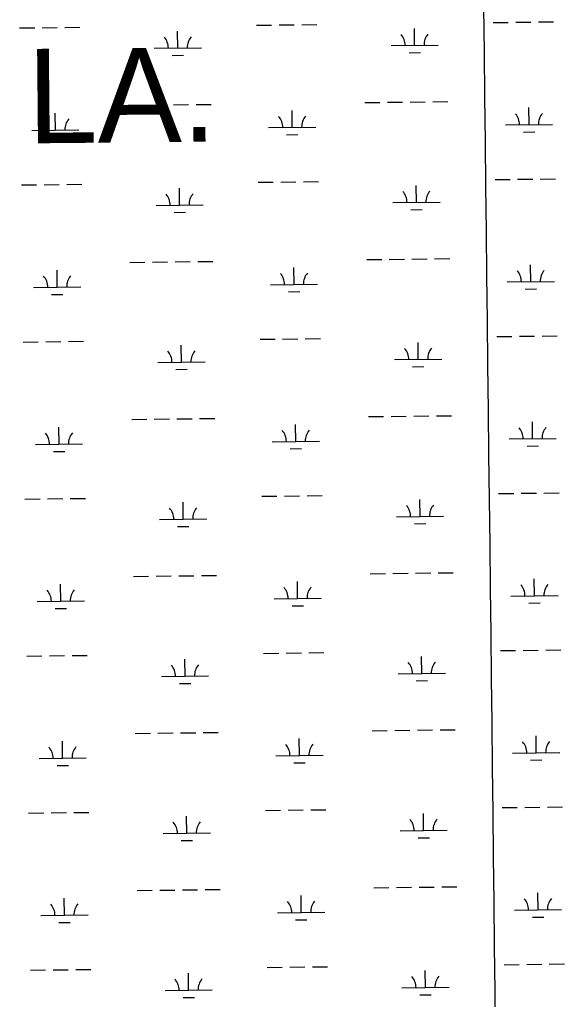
# Model space of a CAD drawing. Extents: x 3678539 to 3716648, y 451386 to 477139.
# Drawn here: x 3686961 to 3688116, y 464890 to 466966 of the extents above; entities that cross this region are included whole.
import ezdxf

# ---------------------------------------------------------------- set-up
doc = ezdxf.new("R2010")
doc.units = 0
for name, color, linetype in [('V-GRID-MAJR', 7, 'Continuous'), ('V-TOPO-GNAM-IDEN', 7, 'Continuous'), ('V-WETL-SWMP', 7, 'Continuous')]:
    doc.layers.add(name, color=color, linetype=linetype)

msp = doc.modelspace()

# ---------------------------------------------------------------- linework, layer by layer
at = {"layer": 'V-GRID-MAJR'}
msp.add_spline([(3688058.923, 456860.782), (3687991.068, 462919.335), (3687923.191, 468979.818), (3687855.313, 475040.309), (3687855.291, 475042.231)], degree=3, dxfattribs=at)
at = {"layer": 'V-WETL-SWMP'}
for p, q in [((3686961.1525815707, 466948.31695062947), (3686993.1504564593, 466948.68463293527)), ((3687009.1493939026, 466948.86847408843), (3687041.1472687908, 466949.2361563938)), ((3687057.146206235, 466949.41999754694), (3687089.1440811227, 466949.7876798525)), ((3687463.027249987, 466954.08390971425), (3687495.0251248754, 466954.45159202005)), ((3687511.0240623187, 466954.6354331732), (3687543.0219372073, 466955.00311547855)), ((3687559.020874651, 466955.18695663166), (3687591.018749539, 466955.55463893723)), ((3687798.382506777, 466911.5043577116), (3687797.968856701, 466947.5019802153)), ((3687964.9019184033, 466959.8508687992), (3687996.8997932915, 466960.218551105)), ((3688012.8987307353, 466960.40239225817), (3688044.8966056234, 466960.7700745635)), ((3688060.8955430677, 466960.9539157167), (3688092.8934179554, 466961.32159802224)), ((3687296.5078383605, 466905.7373986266), (3687296.094188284, 466941.73502113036)), ((3687246.5111588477, 466905.1628950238), (3687346.504517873, 466906.3119022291)), ((3687748.3858272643, 466910.92985410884), (3687848.3791862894, 466912.07886131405)), ((3687284.6859417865, 466890.1695368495), (3687308.684347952, 466890.445298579)), ((3687786.560610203, 466895.9364959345), (3687810.5590163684, 466896.21225766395)), ((3687191.0505832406, 466784.4466830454), (3687223.0484581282, 466784.8143653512)), ((3687239.047395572, 466784.99820650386), (3687271.04527046, 466785.3658888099)), ((3687287.0442079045, 466785.54972996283), (3687319.042082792, 466785.9174122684)), ((3687335.0410202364, 466786.10125342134), (3687367.0388951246, 466786.46893572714)), ((3687692.9252516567, 466790.2136421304), (3687724.923126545, 466790.5813244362)), ((3687740.9220639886, 466790.7651655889), (3687772.919938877, 466791.1328478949)), ((3687788.918876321, 466791.31668904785), (3687820.916751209, 466791.6843713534)), ((3687836.915688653, 466791.8682125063), (3687868.9135635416, 466792.2358948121)), ((3688040.801226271, 466743.4656790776), (3688040.387576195, 466779.4633015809)), ((3687037.051889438, 466731.9317609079), (3687036.6382393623, 466767.9293834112)), ((3687538.9265578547, 466737.69871999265), (3687538.512907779, 466773.6963424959)), ((3687488.929878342, 466737.1242163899), (3687588.9232373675, 466738.2732235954)), ((3687990.8045467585, 466742.8911754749), (3688090.7979057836, 466744.04018268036)), ((3686987.055209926, 466731.3572573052), (3687087.0485689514, 466732.5062645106)), ((3687025.229992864, 466716.3638991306), (3687049.22839903, 466716.6396608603)), ((3687527.1046612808, 466722.1308582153), (3687551.1030674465, 466722.4066199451)), ((3688028.979329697, 466727.89781730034), (3688052.9777358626, 466728.17357903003)), ((3686964.9751104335, 466615.66392100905), (3686996.972985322, 466616.0316033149)), ((3687012.971922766, 466616.215444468), (3687044.9697976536, 466616.58312677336)), ((3687060.968735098, 466616.7669679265), (3687092.9666099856, 466617.1346502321)), ((3687466.8497788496, 466621.43088009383), (3687498.847653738, 466621.79856239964)), ((3687514.846591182, 466621.9824035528), (3687546.84446607, 466622.35008585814)), ((3687562.843403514, 466622.53392701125), (3687594.841278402, 466622.9016093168)), ((3687802.20503564, 466578.8513280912), (3687801.791385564, 466614.8489505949)), ((3687968.724447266, 466627.1978391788), (3688000.722322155, 466627.56552148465)), ((3688016.721259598, 466627.74936263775), (3688048.7191344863, 466628.1170449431)), ((3688064.7180719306, 466628.30088609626), (3688096.7159468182, 466628.66856840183)), ((3687300.3303672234, 466573.08436900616), (3687299.916717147, 466609.08199150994)), ((3687250.333687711, 466572.5098654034), (3687350.3270467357, 466573.6588726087)), ((3687752.208356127, 466578.2768244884), (3687852.2017151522, 466579.42583169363)), ((3687288.5084706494, 466557.5165072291), (3687312.506876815, 466557.7922689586)), ((3687790.383139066, 466563.2834663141), (3687814.381545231, 466563.55922804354)), ((3687194.8731121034, 466451.793653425), (3687226.870986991, 466452.1613357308)), ((3687242.8699244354, 466452.34517688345), (3687274.867799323, 466452.71285918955)), ((3687290.8667367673, 466452.8967003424), (3687322.8646116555, 466453.264382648)), ((3687338.8635490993, 466453.4482238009), (3687370.8614239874, 466453.8159061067)), ((3687696.7477805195, 466457.56061250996), (3687728.745655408, 466457.92829481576)), ((3687744.7445928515, 466458.11213596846), (3687776.74246774, 466458.4798182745)), ((3687792.741405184, 466458.66365942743), (3687824.7392800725, 466459.031341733)), ((3687840.738217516, 466459.2151828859), (3687872.7360924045, 466459.5828651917)), ((3688044.6237551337, 466410.81264945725), (3688044.210105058, 466446.8102719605)), ((3687040.874418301, 466399.2787312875), (3687040.460768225, 466435.2763537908)), ((3687542.7490867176, 466405.04569037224), (3687542.3354366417, 466441.0433128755)), ((3687492.752407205, 466404.4711867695), (3687592.745766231, 466405.620193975)), ((3687994.627075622, 466410.2381458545), (3688094.6204346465, 466411.38715305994)), ((3686990.8777387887, 466398.70422768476), (3687090.8710978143, 466399.8532348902)), ((3687530.9271901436, 466389.4778285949), (3687554.9255963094, 466389.75359032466)), ((3688032.8018585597, 466395.2447876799), (3688056.800264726, 466395.5205494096)), ((3687029.052521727, 466383.7108695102), (3687053.050927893, 466383.9866312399)), ((3686968.7976392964, 466283.01089138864), (3687000.795514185, 466283.3785736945)), ((3687016.794451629, 466283.5624148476), (3687048.792326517, 466283.93009715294)), ((3687064.791263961, 466284.1139383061), (3687096.7891388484, 466284.4816206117)), ((3687470.6723077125, 466288.7778504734), (3687502.670182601, 466289.1455327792)), ((3687518.669120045, 466289.3293739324), (3687550.666994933, 466289.6970562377)), ((3687566.665932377, 466289.88089739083), (3687598.663807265, 466290.2485796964)), ((3687806.027564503, 466246.19829847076), (3687805.613914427, 466282.1959209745)), ((3687972.546976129, 466294.5448095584), (3688004.5448510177, 466294.91249186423)), ((3688020.5437884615, 466295.09633301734), (3688052.541663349, 466295.4640153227)), ((3688068.5406007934, 466295.64785647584), (3688100.5384756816, 466296.0155387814)), ((3687304.152896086, 466240.43133938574), (3687303.73924601, 466276.4289618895)), ((3687254.156216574, 466239.856835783), (3687354.149575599, 466241.00584298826)), ((3687756.0308849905, 466245.623794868), (3687856.024244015, 466246.7728020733)), ((3687292.330999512, 466224.8634776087), (3687316.329405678, 466225.13923933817)), ((3687794.205667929, 466230.63043669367), (3687818.2040740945, 466230.9061984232)), ((3687198.6956409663, 466119.1406238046), (3687230.693515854, 466119.5083061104)), ((3687246.6924532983, 466119.69214726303), (3687278.690328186, 466120.05982956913)), ((3687294.68926563, 466120.243670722), (3687326.6871405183, 466120.6113530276)), ((3687342.6860779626, 466120.7951941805), (3687374.6839528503, 466121.1628764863)), ((3687700.5703093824, 466124.90758288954), (3687732.568184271, 466125.2752651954)), ((3687748.567121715, 466125.45910634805), (3687780.564996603, 466125.8267886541)), ((3687796.563934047, 466126.010629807), (3687828.5618089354, 466126.3783121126)), ((3687844.560746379, 466126.56215326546), (3687876.5586212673, 466126.9298355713)), ((3687044.6969471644, 466066.6257016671), (3687044.283297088, 466102.62332417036)), ((3687546.5716155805, 466072.3926607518), (3687546.1579655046, 466108.3902832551)), ((3688048.4462839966, 466078.15961983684), (3688048.0326339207, 466114.1572423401)), ((3687496.5749360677, 466071.8181571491), (3687596.5682950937, 466072.9671643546)), ((3687998.4496044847, 466077.5851162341), (3688098.44296351, 466078.7341234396)), ((3686994.7002676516, 466066.05119806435), (3687094.693626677, 466067.20020526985)), ((3687534.7497190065, 466056.8247989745), (3687558.748125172, 466057.10056070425)), ((3688036.6243874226, 466062.5917580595), (3688060.622793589, 466062.8675197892)), ((3687032.87505059, 466051.0578398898), (3687056.8734567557, 466051.33360161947)), ((3686972.6201681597, 465950.3578617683), (3687004.618043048, 465950.7255440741)), ((3687020.6169804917, 465950.9093852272), (3687052.6148553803, 465951.27706753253)), ((3687068.613792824, 465951.4609086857), (3687100.6116677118, 465951.82859099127)), ((3687474.494836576, 465956.124820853), (3687506.492711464, 465956.4925031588)), ((3687522.491648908, 465956.67634431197), (3687554.4895237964, 465957.0440266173)), ((3687570.4884612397, 465957.2278677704), (3687602.4863361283, 465957.59555007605)), ((3687809.8500933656, 465913.54526885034), (3687809.4364432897, 465949.54289135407)), ((3687976.3695049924, 465961.891779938), (3688008.367379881, 465962.2594622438)), ((3688024.366317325, 465962.4433033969), (3688056.3641922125, 465962.81098570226)), ((3688072.3631296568, 465962.9948268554), (3688104.3610045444, 465963.362509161)), ((3687307.9754249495, 465907.77830976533), (3687307.561774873, 465943.7759322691)), ((3687257.9787454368, 465907.2038061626), (3687357.972104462, 465908.35281336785)), ((3687759.853413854, 465912.9707652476), (3687859.846772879, 465914.11977245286)), ((3687296.1535283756, 465892.2104479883), (3687320.151934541, 465892.48620971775)), ((3687798.0281967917, 465897.97740707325), (3687822.026602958, 465898.25316880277)), ((3687202.5181698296, 465786.4875941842), (3687234.5160447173, 465786.85527649)), ((3687250.5149821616, 465787.0391176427), (3687282.5128570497, 465787.4067999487)), ((3687298.5117944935, 465787.5906411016), (3687330.5096693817, 465787.95832340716)), ((3687346.508606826, 465788.1421645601), (3687378.506481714, 465788.5098468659)), ((3687704.3928382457, 465792.25455326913), (3687736.390713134, 465792.622235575)), ((3687752.3896505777, 465792.80607672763), (3687784.3875254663, 465793.17375903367)), ((3687800.3864629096, 465793.3576001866), (3687832.384337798, 465793.7252824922)), ((3687848.383275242, 465793.9091236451), (3687880.38115013, 465794.2768059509)), ((3687048.5194760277, 465733.9726720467), (3687048.105825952, 465769.97029454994)), ((3687550.394144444, 465739.7396311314), (3687549.980494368, 465775.7372536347)), ((3688052.26881286, 465745.5065902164), (3688051.855162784, 465781.5042127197)), ((3688002.2721333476, 465744.93208661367), (3688102.265492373, 465746.0810938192)), ((3686998.5227965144, 465733.39816844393), (3687098.5161555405, 465734.54717564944)), ((3687500.397464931, 465739.16512752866), (3687600.3908239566, 465740.31413473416)), ((3687538.57224787, 465724.17176935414), (3687562.5706540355, 465724.44753108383)), ((3688040.446916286, 465729.9387284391), (3688064.4453224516, 465730.21449016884)), ((3687036.6975794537, 465718.40481026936), (3687060.695985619, 465718.6805719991)), ((3686976.4426970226, 465617.70483214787), (3687008.440571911, 465618.07251445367)), ((3687024.4395093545, 465618.2563556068), (3687056.437384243, 465618.6240379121)), ((3687072.436321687, 465618.8078790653), (3687104.4341965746, 465619.17556137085)), ((3687478.3173654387, 465623.4717912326), (3687510.315240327, 465623.8394735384)), ((3687526.3141777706, 465624.02331469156), (3687558.312052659, 465624.3909969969)), ((3687574.310990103, 465624.57483815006), (3687606.308864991, 465624.94252045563)), ((3687813.6726222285, 465580.8922392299), (3687813.2589721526, 465616.8898617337)), ((3687980.1920338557, 465629.2387503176), (3688012.189908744, 465629.6064326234)), ((3688028.1888461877, 465629.79027377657), (3688060.186721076, 465630.15795608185)), ((3688076.1856585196, 465630.341797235), (3688108.1835334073, 465630.7094795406)), ((3687311.797953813, 465575.1252801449), (3687311.3843037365, 465611.1229026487)), ((3687261.8012742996, 465574.5507765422), (3687361.7946333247, 465575.69978374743)), ((3687763.6759427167, 465580.3177356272), (3687863.6693017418, 465581.46674283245)), ((3687299.976057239, 465559.5574183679), (3687323.9744634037, 465559.83318009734)), ((3687801.8507256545, 465565.32437745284), (3687825.8491318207, 465565.60013918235)), ((3687206.3406986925, 465453.83456456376), (3687238.33857358, 465454.20224686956)), ((3687254.3375110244, 465454.38608802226), (3687286.3353859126, 465454.7537703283)), ((3687302.334323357, 465454.9376114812), (3687334.3321982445, 465455.30529378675)), ((3687350.331135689, 465455.4891349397), (3687382.329010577, 465455.8568172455)), ((3687708.215367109, 465459.6015236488), (3687740.2132419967, 465459.9692059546)), ((3687756.2121794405, 465460.1530471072), (3687788.210054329, 465460.52072941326)), ((3687804.208991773, 465460.7045705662), (3687836.206866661, 465461.07225287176)), ((3687852.205804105, 465461.2560940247), (3687884.2036789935, 465461.6237763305)), ((3687052.3420048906, 465401.3196424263), (3687051.9283548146, 465437.31726492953)), ((3687554.2166733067, 465407.086601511), (3687553.8030232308, 465443.0842240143)), ((3688056.091341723, 465412.853560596), (3688055.6776916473, 465448.85118309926)), ((3688006.0946622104, 465412.27905699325), (3688106.088021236, 465413.42806419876)), ((3687002.345325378, 465400.7451388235), (3687102.3386844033, 465401.894146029)), ((3687504.219993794, 465406.51209790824), (3687604.2133528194, 465407.66110511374)), ((3687542.3947767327, 465391.5187397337), (3687566.3931828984, 465391.7945014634)), ((3688044.269445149, 465397.2856988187), (3688068.2678513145, 465397.56146054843)), ((3687040.5201083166, 465385.75178064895), (3687064.5185144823, 465386.0275423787)), ((3686980.2652258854, 465285.05180252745), (3687012.263100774, 465285.41948483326)), ((3687028.2620382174, 465285.6033259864), (3687060.259913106, 465285.97100829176)), ((3687076.25885055, 465286.15484944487), (3687108.256725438, 465286.52253175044)), ((3687482.1398943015, 465290.8187616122), (3687514.13776919, 465291.186443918)), ((3687530.1367066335, 465291.37028507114), (3687562.134581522, 465291.7379673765)), ((3687578.133518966, 465291.92180852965), (3687610.131393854, 465292.2894908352)), ((3687817.495151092, 465248.2392096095), (3687817.081501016, 465284.2368321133)), ((3687984.0145627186, 465296.5857206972), (3688016.0124376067, 465296.953403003)), ((3688032.0113750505, 465297.13724415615), (3688064.0092499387, 465297.5049264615)), ((3688080.008187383, 465297.6887676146), (3688112.00606227, 465298.0564499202)), ((3687315.6204826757, 465242.47225052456), (3687315.2068325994, 465278.4698730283)), ((3687265.6238031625, 465241.8977469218), (3687365.6171621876, 465243.046754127)), ((3687767.4984715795, 465247.66470600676), (3687867.4918306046, 465248.81371321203)), ((3687303.7985861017, 465226.90438874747), (3687327.7969922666, 465227.1801504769)), ((3687805.673254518, 465232.6713478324), (3687829.6716606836, 465232.94710956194)), ((3687210.1632275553, 465121.18153494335), (3687242.1611024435, 465121.54921724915)), ((3687258.1600398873, 465121.73305840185), (3687290.1579147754, 465122.1007407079)), ((3687306.1568522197, 465122.2845818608), (3687338.1547271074, 465122.6522641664)), ((3687354.1536645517, 465122.83610531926), (3687386.15153944, 465123.20378762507)), ((3687712.037895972, 465126.94849402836), (3687744.0357708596, 465127.31617633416)), ((3687760.0347083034, 465127.5000174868), (3687792.032583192, 465127.8676997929)), ((3687808.031520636, 465128.0515409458), (3687840.029395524, 465128.41922325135)), ((3687856.028332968, 465128.6030644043), (3687888.0262078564, 465128.9707467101)), ((3687056.1645337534, 465068.66661280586), (3687055.7508836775, 465104.6642353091)), ((3687558.0392021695, 465074.4335718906), (3687557.6255520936, 465110.4311943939)), ((3688059.913870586, 465080.2005309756), (3688059.50022051, 465116.19815347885)), ((3688009.9171910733, 465079.62602737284), (3688109.910550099, 465080.77503457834)), ((3687006.1678542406, 465068.0921092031), (3687106.1612132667, 465069.2411164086)), ((3687508.042522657, 465073.8590682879), (3687608.0358816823, 465075.00807549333)), ((3687546.2173055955, 465058.8657101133), (3687570.2157117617, 465059.141471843)), ((3688048.091974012, 465064.63266919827), (3688072.0903801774, 465064.908430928)), ((3687044.3426371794, 465053.09875102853), (3687068.341043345, 465053.3745127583)), ((3686984.0877547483, 464952.39877290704), (3687016.085629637, 464952.76645521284)), ((3687032.0845670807, 464952.950296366), (3687064.082441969, 464953.31797867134)), ((3687080.0813794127, 464953.50181982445), (3687112.079254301, 464953.86950213)), ((3687485.9624231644, 464958.16573199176), (3687517.960298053, 464958.53341429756)), ((3687533.959235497, 464958.7172554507), (3687565.957110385, 464959.08493775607)), ((3687581.956047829, 464959.26877890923), (3687613.9539227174, 464959.6364612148)), ((3687987.8370915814, 464963.93269107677), (3688019.83496647, 464964.3003733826)), ((3688035.8339039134, 464964.48421453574), (3688067.8317788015, 464964.8518968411)), ((3688083.830716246, 464965.0357379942), (3688115.828591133, 464965.40342029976)), ((3687319.4430115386, 464909.81922090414), (3687319.029361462, 464945.81684340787)), ((3687821.3176799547, 464915.5861799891), (3687820.904029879, 464951.5838024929)), ((3687771.3210004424, 464915.01167638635), (3687871.3143594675, 464916.1606835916)), ((3687269.446332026, 464909.2447173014), (3687369.4396910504, 464910.3937245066)), ((3687307.6211149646, 464894.25135912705), (3687331.61952113, 464894.5271208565)), ((3687809.4957833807, 464900.01831821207), (3687833.4941895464, 464900.2940799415))]:
    msp.add_line(p, q, dxfattribs=at)
for centre, radius, start, end in [((3687241.2631153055, 466905.5774251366), 35.24628790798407, 359.8865270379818, 41.43018537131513), ((3687351.7416501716, 466906.84691576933), 35.24628790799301, 139.88652460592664, 181.43018293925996), ((3687743.137783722, 466911.34438422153), 35.24628790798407, 359.8865270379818, 41.43018537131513), ((3687853.616318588, 466912.61387485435), 35.24628790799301, 139.88652460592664, 181.43018293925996), ((3687483.6818347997, 466737.53874650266), 35.24628790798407, 359.8865270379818, 41.43018537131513), ((3687594.1603696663, 466738.8082371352), 35.24628790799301, 139.88652460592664, 181.43018293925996), ((3687985.5565032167, 466743.3057055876), 35.24628790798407, 359.8865270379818, 41.43018537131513), ((3688096.0350380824, 466744.5751962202), 35.24628790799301, 139.88652460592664, 181.43018293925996), ((3686981.8071663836, 466731.7717874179), 35.24628790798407, 359.8865270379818, 41.43018537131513), ((3687092.2857012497, 466733.04127805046), 35.24628790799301, 139.88652460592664, 181.43018293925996), ((3687245.0856441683, 466572.92439551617), 35.24628790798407, 359.8865270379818, 41.43018537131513), ((3687355.5641790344, 466574.1938861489), 35.24628790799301, 139.88652460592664, 181.43018293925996), ((3687746.960312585, 466578.6913546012), 35.24628790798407, 359.8865270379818, 41.43018537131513), ((3687857.4388474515, 466579.96084523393), 35.24628790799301, 139.88652460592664, 181.43018293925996), ((3687487.504363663, 466404.88571688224), 35.24628790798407, 359.8865270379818, 41.43018537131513), ((3687597.982898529, 466406.15520751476), 35.24628790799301, 139.88652460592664, 181.43018293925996), ((3687989.3790320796, 466410.6526759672), 35.24628790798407, 359.8865270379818, 41.43018537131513), ((3688099.8575669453, 466411.9221665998), 35.24628790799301, 139.88652460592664, 181.43018293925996), ((3686985.629695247, 466399.11875779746), 35.24628790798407, 359.8865270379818, 41.43018537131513), ((3687096.1082301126, 466400.38824843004), 35.24628790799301, 139.88652460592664, 181.43018293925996), ((3687248.9081730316, 466240.27136589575), 35.24628790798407, 359.8865270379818, 41.43018537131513), ((3687359.3867078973, 466241.5408565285), 35.24628790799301, 139.88652460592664, 181.43018293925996), ((3687750.7828414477, 466246.03832498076), 35.24628790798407, 359.8865270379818, 41.43018537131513), ((3687861.2613763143, 466247.3078156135), 35.24628790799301, 139.88652460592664, 181.43018293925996), ((3687491.326892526, 466072.2326872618), 35.24628790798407, 359.8865270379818, 41.43018537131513), ((3687601.805427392, 466073.50217789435), 35.24628790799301, 139.88652460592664, 181.43018293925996), ((3687993.201560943, 466077.99964634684), 35.24628790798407, 359.8865270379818, 41.43018537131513), ((3688103.680095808, 466079.26913697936), 35.24628790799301, 139.88652460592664, 181.43018293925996), ((3686989.45222411, 466066.4657281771), 35.24628790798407, 359.8865270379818, 41.43018537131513), ((3687099.9307589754, 466067.7352188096), 35.24628790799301, 139.88652460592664, 181.43018293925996), ((3687252.730701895, 465907.61833627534), 35.24628790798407, 359.8865270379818, 41.43018537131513), ((3687363.2092367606, 465908.88782690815), 35.24628790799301, 139.88652460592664, 181.43018293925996), ((3687754.605370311, 465913.38529536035), 35.24628790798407, 359.8865270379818, 41.43018537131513), ((3687865.083905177, 465914.6547859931), 35.24628790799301, 139.88652460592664, 181.43018293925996), ((3687495.149421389, 465739.5796576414), 35.24628790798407, 359.8865270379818, 41.43018537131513), ((3687605.627956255, 465740.84914827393), 35.24628790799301, 139.88652460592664, 181.43018293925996), ((3687997.024089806, 465745.3466167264), 35.24628790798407, 359.8865270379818, 41.43018537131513), ((3688107.5026246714, 465746.61610735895), 35.24628790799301, 139.88652460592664, 181.43018293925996), ((3686993.2747529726, 465733.8126985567), 35.24628790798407, 359.8865270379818, 41.43018537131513), ((3687103.7532878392, 465735.0821891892), 35.24628790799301, 139.88652460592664, 181.43018293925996), ((3687256.553230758, 465574.9653066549), 35.24628790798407, 359.8865270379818, 41.43018537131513), ((3687367.0317656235, 465576.23479728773), 35.24628790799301, 139.88652460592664, 181.43018293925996), ((3687758.427899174, 465580.73226573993), 35.24628790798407, 359.8865270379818, 41.43018537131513), ((3687868.90643404, 465582.0017563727), 35.24628790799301, 139.88652460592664, 181.43018293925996), ((3687498.971950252, 465406.926628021), 35.24628790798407, 359.8865270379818, 41.43018537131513), ((3687609.450485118, 465408.1961186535), 35.24628790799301, 139.88652460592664, 181.43018293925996), ((3688000.8466186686, 465412.693587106), 35.24628790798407, 359.8865270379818, 41.43018537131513), ((3688111.3251535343, 465413.96307773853), 35.24628790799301, 139.88652460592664, 181.43018293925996), ((3686997.0972818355, 465401.1596689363), 35.24628790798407, 359.8865270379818, 41.43018537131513), ((3687107.575816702, 465402.4291595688), 35.24628790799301, 139.88652460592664, 181.43018293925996), ((3687260.3757596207, 465242.3122770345), 35.24628790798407, 359.8865270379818, 41.43018537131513), ((3687370.854294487, 465243.5817676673), 35.24628790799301, 139.88652460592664, 181.43018293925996), ((3687762.250428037, 465248.0792361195), 35.24628790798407, 359.8865270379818, 41.43018537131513), ((3687872.728962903, 465249.3487267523), 35.24628790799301, 139.88652460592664, 181.43018293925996), ((3687502.794479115, 465074.2735984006), 35.24628790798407, 359.8865270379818, 41.43018537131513), ((3687613.273013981, 465075.54308903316), 35.24628790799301, 139.88652460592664, 181.43018293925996), ((3688004.6691475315, 465080.0405574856), 35.24628790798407, 359.8865270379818, 41.43018537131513), ((3688115.1476823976, 465081.3100481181), 35.24628790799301, 139.88652460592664, 181.43018293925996), ((3687000.9198106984, 465068.50663931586), 35.24628790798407, 359.8865270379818, 41.43018537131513), ((3687111.398345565, 465069.7761299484), 35.24628790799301, 139.88652460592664, 181.43018293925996), ((3687264.1982884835, 464909.65924741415), 35.24628790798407, 359.8865270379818, 41.43018537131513), ((3687374.6768233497, 464910.9287380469), 35.24628790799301, 139.88652460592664, 181.43018293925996), ((3687766.0729568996, 464915.4262064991), 35.24628790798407, 359.8865270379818, 41.43018537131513), ((3687876.5514917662, 464916.69569713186), 35.24628790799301, 139.88652460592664, 181.43018293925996)]:
    msp.add_arc(centre, radius, start, end, dxfattribs=at)

# ---------------------------------------------------------------- texts
at = {"layer": 'V-TOPO-GNAM-IDEN'}
msp.add_text('LA.', height=199.99959800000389, rotation=0.543641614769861, dxfattribs=at).set_placement((3686978.224415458, 466703.79240495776))

doc.saveas('drawing.dxf')
